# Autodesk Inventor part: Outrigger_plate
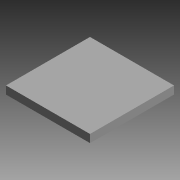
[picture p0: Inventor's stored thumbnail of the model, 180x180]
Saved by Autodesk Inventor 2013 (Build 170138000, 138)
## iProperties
Created: 2012-09
Part Number: Outrigger_plate
Material: Generic
Document SubType Name: Modeling
Designer: yh63
Author: yh63
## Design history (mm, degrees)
sketch "Sketch1"
  geometry: L1 (0, 0)-(203.2, 0); L2 (203.2, 0)-(203.2, -203.2); L3 (203.2, -203.2)-(0, -203.2); L4 (0, -203.2)-(0, 0)
  constraints: 8 end point, 2 parallel, 1 horizontal, 1 perpendicular
  dimensions: "d0" = 203.2 distance of L1.start L1.end; "d1" = 203.2 distance of L3.end L1.start
extrude "Extrusion1" new body sketch "Sketch1" distance "d2" = 19.05; taper "d3" = 0 deg
body "Solid1"
